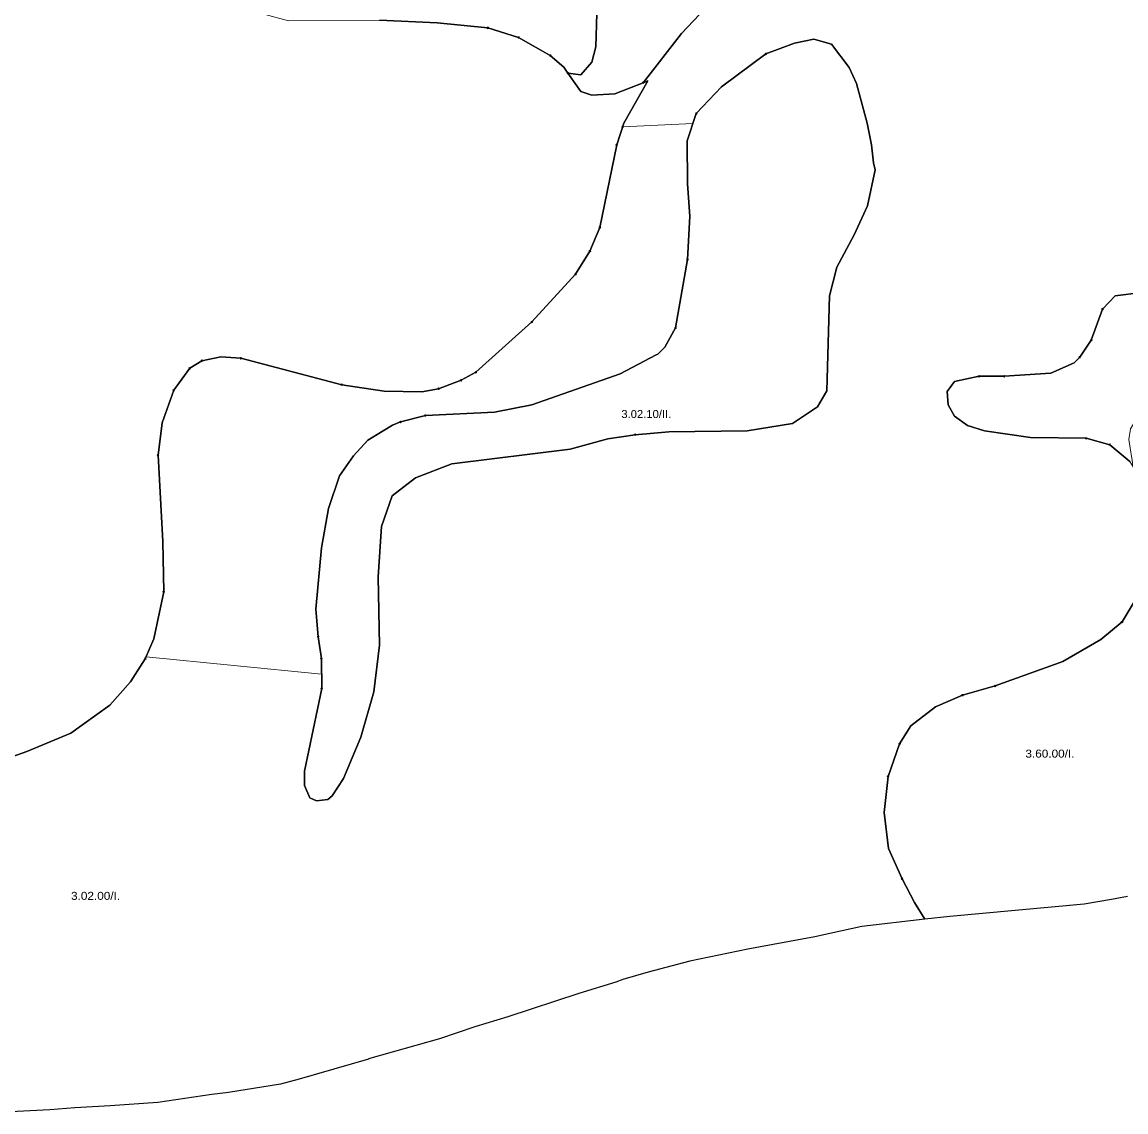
# Model space of a CAD drawing. Extents: x -650455 to -642254, y -1075222 to -1066610.
# Drawn here: x -644838 to -643459, y -1070987 to -1069625 of the extents above; entities that cross this region are included whole.
import ezdxf
from ezdxf.enums import TextEntityAlignment as Align

# ---------------------------------------------------------------- set-up
doc = ezdxf.new("R2010")
doc.units = 0
doc.header["$LTSCALE"] = 4
doc.header["$PDMODE"] = 32
doc.header["$PDSIZE"] = 2
for name, color, linetype, lineweight in [('1', 7, 'Continuous', 25), ('11', 7, 'Continuous', 13), ('12', 7, 'Continuous', 13), ('13', 7, 'Continuous', 13), ('15', 7, 'Continuous', 13)]:
    doc.layers.add(name, color=color, linetype=linetype, lineweight=lineweight)
doc.layers.add('2', color=7, linetype='Continuous')

msp = doc.modelspace()

# ---------------------------------------------------------------- linework, layer by layer
at = {"layer": '1'}
for points in [[(-644673.5, -1070396), (-644661, -1070337.501), (-644662, -1070274.5), (-644668, -1070166.5), (-644663, -1070126), (-644648.5, -1070085.5), (-644628.5, -1070058.001), (-644613.5, -1070048.5), (-644589.5, -1070043.5), (-644564.5, -1070045.5), (-644438.5, -1070078.501), (-644385.5, -1070086.501), (-644338.5, -1070087.501), (-644317.5, -1070083.501), (-644289.5, -1070073), (-644271, -1070063.001), (-644201, -1070000), (-644146.5, -1069940.501), (-644128.5, -1069911.5), (-644116, -1069882), (-644095, -1069778.501), (-644086, -1069751.501), (-644056, -1069698.501), (-644062, -1069701), (-644014, -1069639.5), (-643984, -1069608)], [(-644120, -1069614.5), (-644121, -1069656), (-644126, -1069675.5), (-644140, -1069691.001), (-644156, -1069689), (-644161, -1069681.501), (-644178, -1069667), (-644217.5, -1069644.5), (-644256, -1069632.5), (-644319.5, -1069626.001), (-644391.5, -1069623)], [(-643984, -1069608), (-644014, -1069639.5), (-644062, -1069701), (-644097.5, -1069715.001), (-644126, -1069716.5), (-644140, -1069712), (-644156, -1069689), (-644140, -1069691.001), (-644126, -1069675.5), (-644121, -1069656), (-644120, -1069614.5)], [(-644391.5, -1069623), (-644319.5, -1069626.001), (-644256, -1069632.5), (-644217.5, -1069644.5), (-644178, -1069667), (-644161, -1069681.501), (-644156, -1069689), (-644140, -1069712), (-644126, -1069716.5), (-644097.5, -1069715.001), (-644062, -1069701), (-644056, -1069698.501), (-644086, -1069751.501), (-644095, -1069778.501), (-644116, -1069882), (-644128.5, -1069911.5)], [(-644456, -1070597.001), (-644470, -1070598.5), (-644478.5, -1070595), (-644485, -1070579.5), (-644485, -1070561.501), (-644463.5, -1070458), (-644464, -1070420.5), (-644468, -1070393.5), (-644471, -1070359.001), (-644464, -1070282.5), (-644455, -1070233.001), (-644441.5, -1070192.501), (-644424, -1070167.501), (-644406, -1070148.001), (-644375, -1070129), (-644365, -1070125), (-644334, -1070117), (-644247.5, -1070113), (-644201, -1070103.501), (-644090.5, -1070065), (-644045.5, -1070041), (-644043.5, -1070040.5), (-644035, -1070031.5), (-644021.5, -1070007.5), (-644006.5, -1069922), (-644003.5, -1069868.001), (-644006.5, -1069827.501), (-644007, -1069773.5), (-643995.5, -1069739.501), (-643964, -1069706.001), (-643908.5, -1069665.001), (-643873, -1069651.5), (-643848.5, -1069646.501), (-643826.5, -1069653.001), (-643804.5, -1069682.001), (-643795.5, -1069702.001), (-643782, -1069751.501), (-643776.5, -1069778.501), (-643774, -1069801), (-643772, -1069810)], [(-644456, -1070597.001), (-644450.5, -1070592.501), (-644436.5, -1070570.5), (-644414.5, -1070519), (-644398.5, -1070462.5), (-644391.5, -1070404), (-644393, -1070318.501), (-644389, -1070255.5), (-644375.5, -1070217.501), (-644346.5, -1070195), (-644301, -1070177.5), (-644153, -1070159.001), (-644106, -1070146), (-644072, -1070141), (-644030, -1070137.5), (-643932, -1070136.001), (-643875.5, -1070127.001), (-643844, -1070106), (-643832.5, -1070086.001), (-643829, -1069967.5), (-643820, -1069931.5), (-643798.5, -1069891), (-643781.5, -1069855), (-643772, -1069810), (-643774, -1069801), (-643776.5, -1069778.501), (-643782, -1069751.501), (-643795.5, -1069702.001), (-643804.5, -1069682.001), (-643826.5, -1069653.001), (-643848.5, -1069646.501), (-643873, -1069651.5), (-643908.5, -1069665.001), (-643964, -1069706.001), (-643995.5, -1069739.501), (-644007, -1069773.5), (-644006.5, -1069827.501), (-644003.5, -1069868.001), (-644006.5, -1069922), (-644021.5, -1070007.5)], [(-643772, -1069810), (-643781.5, -1069855), (-643798.5, -1069891), (-643820, -1069931.5), (-643829, -1069967.5), (-643832.5, -1070086.001), (-643844, -1070106), (-643875.5, -1070127.001), (-643932, -1070136.001), (-644030, -1070137.5), (-644072, -1070141), (-644106, -1070146), (-644153, -1070159.001), (-644301, -1070177.5), (-644346.5, -1070195), (-644375.5, -1070217.501), (-644389, -1070255.5), (-644393, -1070318.501), (-644391.5, -1070404), (-644398.5, -1070462.5), (-644414.5, -1070519), (-644436.5, -1070570.5), (-644450.5, -1070592.501), (-644456, -1070597.001)], [(-644128.5, -1069911.5), (-644146.5, -1069940.501), (-644201, -1070000), (-644271, -1070063.001), (-644289.5, -1070073), (-644317.5, -1070083.501), (-644338.5, -1070087.501), (-644385.5, -1070086.501), (-644438.5, -1070078.501), (-644564.5, -1070045.5), (-644589.5, -1070043.5), (-644613.5, -1070048.5), (-644628.5, -1070058.001), (-644648.5, -1070085.5), (-644663, -1070126), (-644668, -1070166.5), (-644662, -1070274.5), (-644661, -1070337.501), (-644673.5, -1070396), (-644684, -1070421), (-644702.5, -1070450), (-644728.5, -1070479.001), (-644777, -1070514), (-644832, -1070537.001), (-644888.5, -1070557.001)], [(-643406.5, -1069959), (-643472, -1069967.5), (-643488, -1069984), (-643502, -1070023.001), (-643516.5, -1070044), (-643523.5, -1070051.001), (-643552.5, -1070064), (-643611, -1070068), (-643642, -1070068), (-643673, -1070074.501), (-643682, -1070087.001), (-643681, -1070103.501), (-643673, -1070118), (-643656.5, -1070129.5), (-643635.5, -1070136.001), (-643578, -1070144.501), (-643508.5, -1070145.5), (-643479, -1070153.5), (-643454, -1070174.5)], [(-643454, -1070174.5), (-643479, -1070153.5), (-643508.5, -1070145.5), (-643578, -1070144.501), (-643635.5, -1070136.001), (-643656.5, -1070129.5), (-643673, -1070118), (-643681, -1070103.501), (-643682, -1070087.001), (-643673, -1070074.501), (-643642, -1070068), (-643611, -1070068), (-643552.5, -1070064), (-643523.5, -1070051.001), (-643516.5, -1070044), (-643502, -1070023.001), (-643488, -1069984), (-643472, -1069967.5), (-643406.5, -1069959)], [(-644021.5, -1070007.5), (-644035, -1070031.5), (-644043.5, -1070040.5), (-644045.5, -1070041), (-644090.5, -1070065), (-644201, -1070103.501), (-644247.5, -1070113), (-644334, -1070117), (-644365, -1070125), (-644375, -1070129), (-644406, -1070148.001), (-644424, -1070167.501), (-644441.5, -1070192.501), (-644455, -1070233.001), (-644464, -1070282.5), (-644471, -1070359.001), (-644468, -1070393.5), (-644464, -1070420.5), (-644463.5, -1070458), (-644485, -1070561.501), (-644485, -1070579.5), (-644478.5, -1070595), (-644470, -1070598.5), (-644456, -1070597.001)], [(-643456.751, -1070718.263), (-643476.945, -1070721.725), (-643511.083, -1070727.58), (-643678.736, -1070743.109), (-643709.901, -1070746.632), (-643723, -1070725.5), (-643738.5, -1070696), (-643755.5, -1070658.001), (-643761, -1070613.001), (-643756, -1070568.001), (-643741.5, -1070527.501), (-643727.5, -1070505), (-643696.5, -1070481), (-643663, -1070466.5), (-643622, -1070455.001), (-643537.5, -1070424.5), (-643490, -1070397), (-643463.5, -1070375.001), (-643431, -1070320.5)], [(-643431, -1070320.5), (-643463.5, -1070375.001), (-643490, -1070397), (-643537.5, -1070424.5)], [(-644888.5, -1070557.001), (-644832, -1070537.001), (-644777, -1070514), (-644728.5, -1070479.001), (-644702.5, -1070450), (-644684, -1070421), (-644673.5, -1070396)], [(-643537.5, -1070424.5), (-643622, -1070455.001), (-643663, -1070466.5), (-643696.5, -1070481), (-643727.5, -1070505), (-643741.5, -1070527.501), (-643756, -1070568.001), (-643761, -1070613.001), (-643755.5, -1070658.001), (-643738.5, -1070696), (-643723, -1070725.5), (-643709.901, -1070746.632), (-643788.642, -1070755.533), (-643815.302, -1070761.461), (-643847.32, -1070768.579), (-643931.146, -1070784.108), (-644003.795, -1070799.018), (-644055.682, -1070812.854), (-644087.39, -1070822.077), (-644096.038, -1070825.105), (-644142.159, -1070839.229), (-644230.942, -1070868.342), (-644272.451, -1070881.027), (-644316.555, -1070896.159), (-644405.049, -1070921.239), (-644404.973, -1070921.58), (-644491.815, -1070946.46), (-644515.164, -1070952.514), (-644580.022, -1070963.036), (-644600.776, -1070965.629), (-644668.228, -1070975.719), (-644727.898, -1070979.754), (-644772.001, -1070982.205), (-644803.133, -1070984.654), (-644852.425, -1070987.393)]]:
    msp.add_lwpolyline(points, dxfattribs=at)
at = {"layer": '11'}
for p, q in [((-644087.496, -1069755.989), (-644095, -1069778.501)), ((-644128.5, -1069911.5), (-644116, -1069882)), ((-644146.5, -1069940.501), (-644201, -1070000)), ((-644201, -1070000), (-644271, -1070063.001)), ((-643502, -1070023.001), (-643516.5, -1070044)), ((-644628.5, -1070058.001), (-644613.5, -1070048.5)), ((-644271, -1070063.001), (-644289.5, -1070073)), ((-644289.5, -1070073), (-644317.5, -1070083.501)), ((-644683.012, -1070418.648), (-644684, -1070421)), ((-643741.5, -1070527.501), (-643756, -1070568.001))]:
    msp.add_line(p, q, dxfattribs=at)
for points in [[(-644217.5, -1069644.5), (-644256, -1069632.5), (-644319.5, -1069626.001), (-644391.5, -1069623), (-644505, -1069623.5), (-644549.5, -1069611.5), (-644578.5, -1069593.001)], [(-643984, -1069608), (-644014, -1069639.5), (-644062, -1069701), (-644056, -1069698.501), (-644086, -1069751.501), (-644087.496, -1069755.989), (-643999.727, -1069751.999), (-643995.5, -1069739.501)], [(-644062, -1069701), (-644097.5, -1069715.001), (-644126, -1069716.5), (-644140, -1069712), (-644156, -1069689), (-644161, -1069681.501), (-644178, -1069667), (-644217.5, -1069644.5)], [(-643908.5, -1069665.001), (-643873, -1069651.5), (-643848.5, -1069646.501), (-643826.5, -1069653.001), (-643804.5, -1069682.001), (-643795.5, -1069702.001), (-643782, -1069751.501), (-643776.5, -1069778.501), (-643774, -1069801), (-643772, -1069810), (-643781.5, -1069855), (-643798.5, -1069891), (-643820, -1069931.5), (-643829, -1069967.5), (-643832.5, -1070086.001), (-643844, -1070106), (-643875.5, -1070127.001), (-643932, -1070136.001), (-644030, -1070137.5), (-644072, -1070141), (-644106, -1070146), (-644153, -1070159.001), (-644301, -1070177.5), (-644346.5, -1070195), (-644375.5, -1070217.501), (-644389, -1070255.5), (-644393, -1070318.501), (-644391.5, -1070404), (-644398.5, -1070462.5), (-644414.5, -1070519), (-644436.5, -1070570.5), (-644450.5, -1070592.501), (-644456, -1070597.001), (-644470, -1070598.5), (-644478.5, -1070595), (-644485, -1070579.5), (-644485, -1070561.501), (-644463.5, -1070458), (-644463.738, -1070440.148), (-644683.012, -1070418.648)], [(-643995.5, -1069739.501), (-643964, -1069706.001), (-643908.5, -1069665.001)], [(-644116, -1069882), (-644095, -1069778.501), (-644086, -1069751.501), (-644056, -1069698.501), (-644062, -1069701)], [(-644365, -1070125), (-644334, -1070117), (-644247.5, -1070113), (-644201, -1070103.501), (-644090.5, -1070065), (-644045.5, -1070041), (-644043.5, -1070040.5), (-644035, -1070031.5), (-644021.5, -1070007.5), (-644006.5, -1069922), (-644003.5, -1069868.001), (-644006.5, -1069827.501), (-644007, -1069773.5), (-643999.727, -1069751.999), (-644087.496, -1069755.989)], [(-644095, -1069778.501), (-644116, -1069882), (-644128.5, -1069911.5), (-644146.5, -1069940.501)], [(-644438.5, -1070078.501), (-644385.5, -1070086.501), (-644338.5, -1070087.501), (-644317.5, -1070083.501), (-644289.5, -1070073), (-644271, -1070063.001), (-644201, -1070000), (-644146.5, -1069940.501), (-644128.5, -1069911.5)], [(-643266.5, -1069951), (-643356.5, -1069957.501), (-643406.5, -1069959), (-643472, -1069967.5), (-643488, -1069984), (-643502, -1070023.001)], [(-643488, -1069984), (-643472, -1069967.5), (-643406.5, -1069959)], [(-643611, -1070068), (-643552.5, -1070064), (-643523.5, -1070051.001), (-643516.5, -1070044), (-643502, -1070023.001), (-643488, -1069984)], [(-644564.5, -1070045.5), (-644589.5, -1070043.5), (-644613.5, -1070048.5), (-644628.5, -1070058.001), (-644648.5, -1070085.5)], [(-644613.5, -1070048.5), (-644589.5, -1070043.5), (-644564.5, -1070045.5), (-644438.5, -1070078.501)], [(-643516.5, -1070044), (-643523.5, -1070051.001), (-643552.5, -1070064), (-643611, -1070068), (-643642, -1070068)], [(-645087, -1070571), (-645008.5, -1070579.5), (-644982, -1070577.501), (-644888.5, -1070557.001), (-644832, -1070537.001), (-644777, -1070514), (-644728.5, -1070479.001), (-644702.5, -1070450), (-644684, -1070421), (-644673.5, -1070396), (-644661, -1070337.501), (-644662, -1070274.5), (-644668, -1070166.5), (-644663, -1070126), (-644648.5, -1070085.5), (-644628.5, -1070058.001)], [(-644317.5, -1070083.501), (-644338.5, -1070087.501), (-644385.5, -1070086.501), (-644438.5, -1070078.501), (-644564.5, -1070045.5)], [(-643508.5, -1070145.5), (-643578, -1070144.501), (-643635.5, -1070136.001), (-643656.5, -1070129.5), (-643673, -1070118), (-643681, -1070103.501), (-643682, -1070087.001), (-643673, -1070074.501), (-643642, -1070068), (-643611, -1070068)], [(-643642, -1070068), (-643673, -1070074.501), (-643682, -1070087.001), (-643681, -1070103.501), (-643673, -1070118), (-643656.5, -1070129.5), (-643635.5, -1070136.001), (-643578, -1070144.501), (-643508.5, -1070145.5), (-643479, -1070153.5)], [(-644648.5, -1070085.5), (-644663, -1070126), (-644668, -1070166.5)], [(-644468, -1070393.5), (-644471, -1070359.001), (-644464, -1070282.5), (-644455, -1070233.001), (-644441.5, -1070192.501), (-644424, -1070167.501), (-644406, -1070148.001), (-644375, -1070129), (-644365, -1070125)], [(-643479, -1070153.5), (-643454, -1070174.5), (-643449.5, -1070181.001), (-643455, -1070147.001), (-643453, -1070133.5), (-643445, -1070120.5), (-643438, -1070118.501), (-643398.5, -1070119.501), (-643293.5, -1070129.5), (-643228.5, -1070130)], [(-643622, -1070455.001), (-643537.5, -1070424.5), (-643490, -1070397), (-643463.5, -1070375.001), (-643431, -1070320.5), (-643428, -1070315.5), (-643417, -1070268.501), (-643419.5, -1070239), (-643431.5, -1070205.5), (-643449.5, -1070181.001), (-643454, -1070174.5), (-643479, -1070153.5), (-643508.5, -1070145.5)], [(-644668, -1070166.5), (-644662, -1070274.5), (-644661, -1070337.501)], [(-643431, -1070320.5), (-643463.5, -1070375.001)], [(-644661, -1070337.501), (-644673.5, -1070396), (-644683.012, -1070418.648), (-644463.738, -1070440.148), (-644464, -1070420.5), (-644468, -1070393.5)], [(-643463.5, -1070375.001), (-643490, -1070397), (-643537.5, -1070424.5), (-643622, -1070455.001), (-643663, -1070466.5)], [(-644684, -1070421), (-644702.5, -1070450), (-644728.5, -1070479.001), (-644777, -1070514), (-644832, -1070537.001), (-644888.5, -1070557.001), (-644982, -1070577.501), (-645008.5, -1070579.5), (-645087, -1070571), (-645188.5, -1070544.501), (-645179.5, -1070566.5)], [(-644852.425, -1070987.393), (-644803.133, -1070984.654), (-644772.001, -1070982.205), (-644727.898, -1070979.754), (-644668.228, -1070975.719), (-644600.776, -1070965.629), (-644580.022, -1070963.036), (-644515.164, -1070952.514), (-644491.815, -1070946.46), (-644404.973, -1070921.58), (-644405.049, -1070921.239), (-644316.555, -1070896.159), (-644272.451, -1070881.027), (-644230.942, -1070868.342), (-644142.159, -1070839.229), (-644096.038, -1070825.105), (-644087.39, -1070822.077), (-644055.682, -1070812.854), (-644003.795, -1070799.018), (-643931.146, -1070784.108), (-643847.32, -1070768.579), (-643815.302, -1070761.461), (-643788.642, -1070755.533), (-643709.901, -1070746.632), (-643723, -1070725.5), (-643738.5, -1070696), (-643755.5, -1070658.001), (-643761, -1070613.001), (-643756, -1070568.001), (-643741.5, -1070527.501), (-643727.5, -1070505), (-643696.5, -1070481), (-643663, -1070466.5), (-643622, -1070455.001)], [(-643663, -1070466.5), (-643696.5, -1070481), (-643727.5, -1070505), (-643741.5, -1070527.501)], [(-643756, -1070568.001), (-643761, -1070613.001), (-643755.5, -1070658.001), (-643738.5, -1070696)], [(-643738.5, -1070696), (-643723, -1070725.5), (-643709.901, -1070746.632), (-643678.736, -1070743.109), (-643511.083, -1070727.58), (-643476.945, -1070721.725), (-643456.751, -1070718.263)]]:
    msp.add_lwpolyline(points, dxfattribs=at)
for p in [(-644217.5, -1069644.5), (-643908.5, -1069665.001), (-644062, -1069701), (-643995.5, -1069739.501), (-644087.496, -1069755.989), (-644095, -1069778.501), (-644116, -1069882), (-644128.5, -1069911.5), (-644146.5, -1069940.501), (-643488, -1069984), (-644201, -1070000), (-643502, -1070023.001), (-644564.5, -1070045.5), (-643516.5, -1070044), (-644628.5, -1070058.001), (-644613.5, -1070048.5), (-644289.5, -1070073), (-644271, -1070063.001), (-643642, -1070068), (-643611, -1070068), (-644648.5, -1070085.5), (-644438.5, -1070078.501), (-644317.5, -1070083.501), (-644365, -1070125), (-643508.5, -1070145.5), (-643479, -1070153.5), (-644668, -1070166.5), (-644661, -1070337.501), (-643463.5, -1070375.001), (-644468, -1070393.5), (-644684, -1070421), (-643622, -1070455.001), (-643663, -1070466.5), (-643741.5, -1070527.501), (-643756, -1070568.001), (-643738.5, -1070696)]:
    msp.add_point(p, dxfattribs=at)
at = {"layer": '12'}
msp.add_line((-644006.5, -1069922), (-644021.5, -1070007.5), dxfattribs=at)
for points in [[(-644072, -1070141), (-644030, -1070137.5), (-643932, -1070136.001), (-643875.5, -1070127.001), (-643844, -1070106), (-643832.5, -1070086.001), (-643829, -1069967.5), (-643820, -1069931.5), (-643798.5, -1069891), (-643781.5, -1069855), (-643772, -1069810), (-643774, -1069801), (-643776.5, -1069778.501), (-643782, -1069751.501), (-643795.5, -1069702.001), (-643804.5, -1069682.001), (-643826.5, -1069653.001), (-643848.5, -1069646.501), (-643873, -1069651.5), (-643908.5, -1069665.001), (-643964, -1069706.001), (-643995.5, -1069739.501)], [(-643995.5, -1069739.501), (-644007, -1069773.5), (-644006.5, -1069827.501), (-644003.5, -1069868.001), (-644006.5, -1069922)], [(-644021.5, -1070007.5), (-644035, -1070031.5), (-644043.5, -1070040.5), (-644045.5, -1070041), (-644090.5, -1070065), (-644201, -1070103.501), (-644247.5, -1070113), (-644334, -1070117)], [(-644334, -1070117), (-644365, -1070125), (-644375, -1070129), (-644406, -1070148.001), (-644424, -1070167.501), (-644441.5, -1070192.501), (-644455, -1070233.001), (-644464, -1070282.5), (-644471, -1070359.001), (-644468, -1070393.5), (-644464, -1070420.5)], [(-644463.5, -1070458), (-644485, -1070561.501), (-644485, -1070579.5), (-644478.5, -1070595), (-644470, -1070598.5), (-644456, -1070597.001), (-644450.5, -1070592.501), (-644436.5, -1070570.5), (-644414.5, -1070519), (-644398.5, -1070462.5), (-644391.5, -1070404), (-644393, -1070318.501), (-644389, -1070255.5), (-644375.5, -1070217.501), (-644346.5, -1070195), (-644301, -1070177.5), (-644153, -1070159.001), (-644106, -1070146), (-644072, -1070141)], [(-644464, -1070420.5), (-644463.998, -1070420.656), (-644463.738, -1070440.148), (-644463.5, -1070458)]]:
    msp.add_lwpolyline(points, dxfattribs=at)
for p in [(-643995.5, -1069739.501), (-644006.5, -1069922), (-644021.5, -1070007.5), (-644334, -1070117), (-644072, -1070141), (-644464, -1070420.5), (-644463.5, -1070458)]:
    msp.add_point(p, dxfattribs=at)
at = {"layer": '13'}
msp.add_lwpolyline([(-644212, -1069486.5), (-644184.5, -1069493.5), (-644171, -1069502.5), (-644155, -1069523), (-644129, -1069578.5), (-644120, -1069614.5), (-644121, -1069656), (-644126, -1069675.5), (-644140, -1069691.001), (-644156, -1069689), (-644140, -1069712), (-644126, -1069716.5), (-644097.5, -1069715.001), (-644062, -1069701), (-644014, -1069639.5), (-643984, -1069608)], dxfattribs=at)
at = {"layer": '15'}
msp.add_line((-644319.5, -1069626.001), (-644256, -1069632.5), dxfattribs=at)
for points in [[(-644156, -1069689), (-644140, -1069691.001), (-644126, -1069675.5), (-644121, -1069656), (-644120, -1069614.5)], [(-644391.5, -1069623), (-644319.5, -1069626.001)], [(-644256, -1069632.5), (-644217.5, -1069644.5), (-644178, -1069667)], [(-644178, -1069667), (-644161, -1069681.501), (-644156, -1069689)]]:
    msp.add_lwpolyline(points, dxfattribs=at)
for p in [(-644256, -1069632.5), (-644178, -1069667), (-644156, -1069689)]:
    msp.add_point(p, dxfattribs=at)

# ---------------------------------------------------------------- texts
at = {"layer": '2'}
for s, width, p in [('3.02.10/II.', 1.05, (-644057.987, -1070120.135)), ('3.60.00/I.', 1.1, (-643553.671, -1070544.564)), ('3.02.00/I.', 1.1, (-644746.083, -1070722.334))]:
    msp.add_text(s, height=10, dxfattribs=dict(at, width=width)).set_placement(p, align=Align.CENTER)

doc.saveas('drawing.dxf')
